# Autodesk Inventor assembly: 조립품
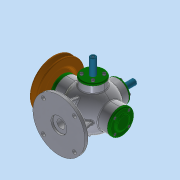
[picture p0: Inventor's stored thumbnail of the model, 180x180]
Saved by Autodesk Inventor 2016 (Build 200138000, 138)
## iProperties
Created: 2019-11
Part Number: 조립품
Material: 일반
Document SubType Name: Assembly
Designer: user
Author: user
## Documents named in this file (17)
- C:\Users\user\Desktop\391120V1009\조립품.iam
- C:\Users\user\Desktop\391120V1009\V-벨트풀리.ipt
- C:\Users\user\Desktop\391120V1009\너트 M8x1.ipt
- C:\Users\user\Desktop\391120V1009\뒤커버.ipt
- C:\Users\user\Desktop\391120V1009\베어링 6202.ipt
- C:\Users\user\Desktop\391120V1009\본체.ipt
- C:\Users\user\Desktop\391120V1009\본체커버.ipt
- C:\Users\user\Desktop\391120V1009\볼트 M4.ipt
- C:\Users\user\Desktop\391120V1009\스프링1.ipt
- C:\Users\user\Desktop\391120V1009\스프링2.ipt
- C:\Users\user\Desktop\391120V1009\슬라이드 커버.ipt
- C:\Users\user\Desktop\391120V1009\슬라이드.ipt
- C:\Users\user\Desktop\391120V1009\앞커버.ipt
- C:\Users\user\Desktop\391120V1009\오일 실.ipt
- C:\Users\user\Desktop\391120V1009\와셔 8x17.ipt
- C:\Users\user\Desktop\391120V1009\축.ipt
- C:\Users\user\Desktop\391120V1009\키 4x4.ipt
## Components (1 placed, 1 different names)
1. V-벨트풀리:1 — 플러쉬:1
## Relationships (1: Flush 1)
- 플러쉬:1 [Flush]: V-벨트풀리:1
